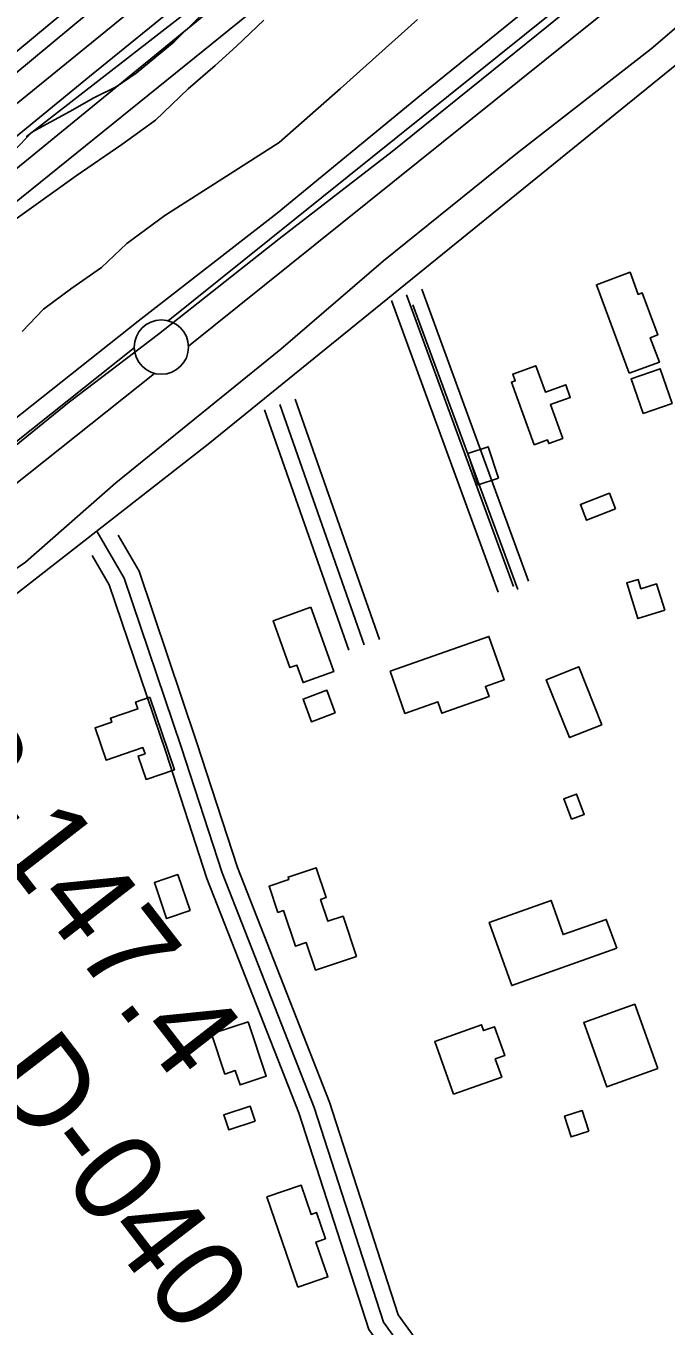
# Model space of a CAD drawing. Extents: x 3477039 to 3515015, y 546746 to 572297.
# Drawn here: x 3484351 to 3484941, y 556246 to 557444 of the extents above; entities that cross this region are included whole.
import ezdxf

# ---------------------------------------------------------------- set-up
doc = ezdxf.new("R2010")
doc.units = 0
for name, color, linetype in [('V-BLDG-OTLN', 7, 'Continuous'), ('V-FLOD-BASE', 7, 'Continuous'), ('V-LEVE-TOET', 7, 'Continuous'), ('V-RIVR-EDGE', 7, 'Continuous'), ('V-RIVR-RANG-IDEN', 7, 'Continuous'), ('V-ROAD-CNTR', 7, 'Continuous'), ('V-RRAP-RVMT', 7, 'Continuous'), ('V-RRAP-RVMT-IDEN', 7, 'Continuous'), ('V-SITE-VEGE', 7, 'Continuous'), ('V-SURV-LINE', 7, 'Continuous'), ('V-TOPO-DPTH', 7, 'Continuous'), ('V-TOPO-MINR', 7, 'Continuous'), ('V-TOPO-WATR', 7, 'Continuous')]:
    doc.layers.add(name, color=color, linetype=linetype)

msp = doc.modelspace()

# ---------------------------------------------------------------- linework, layer by layer
at = {"layer": 'V-BLDG-OTLN'}
for points in [[(3484906.9, 557124.2), (3484876.6, 557205.8), (3484907.6, 557217.3), (3484915.1, 557196.8), (3484918.8, 557198.2), (3484933.1, 557159.6), (3484926.3, 557157), (3484934.7, 557134.5)], [(3484819.3, 557058.4), (3484798.3, 557115.9), (3484801.8, 557117.2), (3484799.5, 557123.5), (3484820.7, 557131.2), (3484829.6, 557106.8), (3484848.4, 557113.6), (3484852.6, 557102), (3484834.2, 557095.3), (3484845.6, 557064.2), (3484832.7, 557059.5), (3484831.5, 557062.8)], [(3484919.8, 557087.2), (3484908.7, 557119.2), (3484935.3, 557128.4), (3484946.4, 557096.5)], [(3484786.4, 557027.5), (3484767.7, 557021.3), (3484758.1, 557050.3), (3484776.9, 557056.5)], [(3484894.2, 556999.2), (3484867.5, 556988.8), (3484861.9, 557003.4), (3484888.6, 557013.7)], [(3484939.7, 556905.9), (3484914.9, 556898.2), (3484904.6, 556931.1), (3484915.1, 556934.3), (3484917.7, 556925.7), (3484932.1, 556930.2)], [(3484613.4, 556908.6), (3484634.6, 556849.4), (3484606.3, 556839.3), (3484600.6, 556855.3), (3484594.3, 556853.1), (3484578.9, 556896.2)], [(3484686.5, 556849.6), (3484777.6, 556881.7), (3484791.6, 556841.7), (3484774.4, 556835.7), (3484777.7, 556826.3), (3484734.2, 556811), (3484730.5, 556821.5), (3484700.2, 556810.8)], [(3484881.6, 556800.4), (3484851.8, 556788.5), (3484830.4, 556841.9), (3484860.3, 556853.8)], [(3484636, 556811.3), (3484614, 556803.2), (3484606.4, 556824), (3484628.3, 556832.1)], [(3484465.1, 556825.7), (3484487.8, 556758.9), (3484461.7, 556750), (3484454.3, 556771.5), (3484460.8, 556773.7), (3484458.8, 556779.4), (3484424.8, 556767.8), (3484414.7, 556797.6), (3484430, 556802.8), (3484428.8, 556806.3), (3484454.2, 556815), (3484452, 556821.3)], [(3484853.6, 556713.4), (3484846.6, 556732.1), (3484858.4, 556736.5), (3484865.4, 556717.8)], [(3484502.2, 556629.2), (3484480.6, 556621.8), (3484469.3, 556655), (3484490.9, 556662.4)], [(3484655.6, 556587), (3484617.8, 556574.4), (3484609.3, 556599.7), (3484599.3, 556596.3), (3484588.3, 556629.1), (3484583.1, 556627.4), (3484575, 556651.6), (3484593.2, 556657.7), (3484592.5, 556660), (3484618.3, 556668.7), (3484627.6, 556641.1), (3484622.5, 556639.3), (3484629.2, 556619.3), (3484643.2, 556624)], [(3484895.3, 556594.4), (3484798.7, 556560), (3484777.9, 556618.2), (3484834.8, 556638.5), (3484846, 556607), (3484885.7, 556621.1)], [(3484933.3, 556483.6), (3484886.3, 556466.7), (3484865, 556526.1), (3484912, 556542.9)], [(3484555.7, 556526.7), (3484572.4, 556476.6), (3484548.3, 556468.5), (3484543.9, 556481.7), (3484534.4, 556478.5), (3484522.1, 556515.5)], [(3484745.1, 556460), (3484727.7, 556508.6), (3484770.8, 556523.9), (3484772.7, 556518.6), (3484782.7, 556522.2), (3484792.2, 556495.6), (3484783.4, 556492.5), (3484789.4, 556475.8)], [(3484562.2, 556435.1), (3484537.9, 556427.1), (3484533.3, 556440.9), (3484557.7, 556448.9)], [(3484869.7, 556425.8), (3484853.3, 556420.6), (3484847.3, 556439.8), (3484863.6, 556444.9)], [(3484601.4, 556282.1), (3484573, 556365.3), (3484604.6, 556376.1), (3484613.7, 556349.3), (3484618.6, 556351), (3484626.9, 556326.8), (3484618.2, 556323.8), (3484629.2, 556291.6)]]:
    msp.add_lwpolyline(points, close=True, dxfattribs=at)
at = {"layer": 'V-FLOD-BASE'}
for points in [[(3484584.2, 557248.1), (3484688.5, 557328.6), (3484832.6, 557444.5), (3484998.5, 557579.6), (3485118.7, 557679.8), (3485220.8, 557762.3)], [(3484584.2, 557248.1), (3484473, 557160.1), (3484391.2, 557098), (3484296, 557020.8), (3484214.8, 556958.1), (3484134.4, 556892.5), (3484070.7, 556842), (3484011.2, 556794.2), (3483940.6, 556737.5), (3483875.5, 556687), (3483799.9, 556624.2), (3483711.8, 556555.2), (3483611.7, 556476.8), (3483550.1, 556427.6), (3483472.5, 556367.5), (3483388.5, 556299.9), (3483319.3, 556245.3), (3483258.4, 556198.9), (3483194, 556144.3), (3483180.7, 556133.4)]]:
    msp.add_lwpolyline(points, dxfattribs=at)
at = {"layer": 'V-LEVE-TOET'}
for points in [[(3485177.7, 557755.5), (3485047.2, 557648.6), (3484890.4, 557523), (3484715.6, 557381.2), (3484582.4, 557271.7)], [(3484585.8, 557146.3), (3484680.4, 557227.8), (3484803.9, 557327.4), (3484927, 557423), (3485014.5, 557498.3), (3485065.3, 557537.9), (3485095.1, 557555.9), (3485107.2, 557560.7), (3485132.6, 557574.7), (3485167.1, 557598.2), (3485216, 557644.1), (3485266.1, 557696.4), (3485335.9, 557752.6)], [(3483140.8, 556159.5), (3483158.3, 556171.7), (3483165.9, 556174.8), (3483178.5, 556179.8), (3483192.4, 556181), (3483207, 556185.7), (3483253.1, 556217), (3483386.1, 556325.6), (3483505, 556421.9), (3483623.3, 556515.4), (3483740.1, 556608.3), (3483905.9, 556740), (3484042.4, 556847.9), (3484238.9, 557001.4), (3484454.4, 557172.1), (3484582.4, 557271.7)], [(3484585.8, 557146.3), (3484433.9, 557023.3), (3484350.6, 556950.2), (3484272.3, 556896.4), (3484164, 556818), (3484079.9, 556744.9), (3484015.6, 556695), (3483932.3, 556629.5), (3483839.3, 556558.6), (3483743.5, 556482.1), (3483676.9, 556425.4), (3483601.3, 556360.5), (3483551, 556324.3), (3483476.9, 556269.1), (3483403.4, 556209), (3483350.2, 556166.7), (3483302.6, 556125), (3483259.1, 556084.6), (3483213, 556049.8), (3483163.2, 556005.4)]]:
    msp.add_lwpolyline(points, dxfattribs=at)
at = {"layer": 'V-RIVR-EDGE'}
msp.add_lwpolyline([(3483504.1, 556660.2), (3483576.2, 556716.7), (3483682.7, 556810.1), (3483737.5, 556864.6), (3483810.3, 556925.1), (3483854.2, 556961.6), (3483939, 557022.6), (3484006.4, 557088.5), (3484040.1, 557123.2), (3484070.2, 557141.7), (3484108.1, 557171.1), (3484149, 557205.2), (3484189.9, 557236.9), (3484233.1, 557256.6), (3484300.5, 557304.5), (3484339.6, 557328.4), (3484356.4, 557346.4), (3484391.3, 557365.5), (3484413.5, 557378), (3484434, 557388.2), (3484452.6, 557400.7), (3484487.5, 557429.5), (3484527.2, 557469)], dxfattribs=at)
at = {"layer": 'V-ROAD-CNTR'}
for points in [[(3484980, 557432.6), (3484518.9, 557058.8), (3484236.1, 556838.3), (3484046.6, 556689.6), (3483814.6, 556500.6), (3483673.5, 556390.5), (3483557.4, 556297.9)], [(3484980, 557432.6), (3484518.9, 557058.8), (3484236.1, 556838.3), (3484046.6, 556689.6), (3483814.6, 556500.6), (3483673.5, 556390.5), (3483557.4, 556297.9)], [(3484715.8, 557201.7), (3484814.2, 556932.8)], [(3484687.7, 557191.4), (3484786, 556922.5)], [(3484701.7, 557196.6), (3484800.1, 556927.6)], [(3484707.6, 557187.4), (3484804.3, 556925.1)], [(3484585, 557095.3), (3484662.5, 556874)], [(3484599.1, 557100.3), (3484676.7, 556878.9)], [(3484570.8, 557090.4), (3484648.4, 556869)], [(3484416.3, 556978.8), (3484441.4, 556935.5), (3484494.1, 556780), (3484531.9, 556663.8), (3484616.6, 556447.7), (3484680.4, 556250), (3484793.8, 556093.4)], [(3484435.9, 556975.1), (3484455.2, 556941.8), (3484508.3, 556784.7), (3484546, 556668.9), (3484630.8, 556452.8), (3484693.9, 556256.8), (3484812, 556093.8)], [(3484412, 556956.4), (3484427.7, 556929.3), (3484479.9, 556775.3), (3484517.8, 556658.8), (3484602.5, 556442.7), (3484666.8, 556243.1), (3484782, 556084.1)]]:
    msp.add_lwpolyline(points, dxfattribs=at)
at = {"layer": 'V-RRAP-RVMT'}
msp.add_line((3484565.6, 557508.7), (3484351.1, 557342.1), dxfattribs=at)
at = {"layer": 'V-SITE-VEGE'}
for points in [[(3484333.5, 557260.4), (3484397.3, 557306.2), (3484439.4, 557334.9), (3484470.3, 557357.5), (3484500.6, 557386.4), (3484525.2, 557407.7), (3484544.9, 557425.5), (3484570.2, 557449.6)], [(3484711.8, 557450.1), (3484640.9, 557386.5), (3484584.2, 557336.7), (3484535.8, 557305.9), (3484479, 557269.7), (3484443.9, 557243.7), (3484420.7, 557221.7), (3484393.3, 557202.6), (3484367.3, 557183.4), (3484347.6, 557162.8)]]:
    msp.add_lwpolyline(points, dxfattribs=at)
at = {"layer": 'V-SURV-LINE'}
for points in [[(3484482, 557172.5), (3485468.6, 557964.5)], [(3484482, 557172.5), (3485468.6, 557964.5)], [(3485487.4, 557941.1), (3484500.7, 557149.1)], [(3485487.4, 557941.1), (3484500.7, 557149.1)], [(3483197.5, 556150.5), (3484450.8, 557147.6)], [(3483197.5, 556150.5), (3484450.8, 557147.6)], [(3484469.5, 557124.1), (3483216.2, 556127)], [(3484469.5, 557124.1), (3483216.2, 556127)]]:
    msp.add_lwpolyline(points, dxfattribs=at)
msp.add_circle((3484475.8, 557148.3), 25, dxfattribs=at)
at = {"layer": 'V-TOPO-DPTH'}
for points in [[(3484942.7, 557828.7), (3484926.3, 557815.5), (3484688.1, 557623.6), (3484595.1, 557548.5), (3484502.2, 557473.2), (3484409.6, 557397.7), (3484317, 557322.1), (3484180, 557209.7), (3484156.1, 557190.1), (3484132.2, 557170.5), (3484108.4, 557150.9), (3484084.5, 557131.3), (3483890.2, 556971.2), (3483795.1, 556892.4), (3483700.2, 556813.4), (3483605.8, 556733.8), (3483511.6, 556654), (3483352.1, 556517.9), (3483337.9, 556505.8), (3483323.9, 556493.6), (3483310, 556481.2), (3483296.1, 556468.8), (3483202.1, 556383.8), (3483141.3, 556328.9)], [(3484457.6, 557497.1), (3484124.3, 557220.5)], [(3484124.3, 557220.5), (3484457.6, 557497.1)]]:
    msp.add_lwpolyline(points, dxfattribs=at)
at = {"layer": 'V-TOPO-MINR'}
for points in [[(3483090.1, 556309.6), (3483264.9, 556471.2), (3483287.3, 556491.7), (3483309.8, 556512), (3483332.5, 556532.2), (3483355.3, 556552.2), (3483418.9, 556607.3), (3483473.8, 556654.6), (3483528.9, 556701.6), (3483584.4, 556748.2), (3483640.1, 556794.5), (3484052.7, 557134.8), (3484085.4, 557161.7), (3484118.1, 557188.7), (3484150.8, 557215.7), (3484183.6, 557242.6), (3484190, 557247.9), (3484226, 557277.4), (3484262, 557306.9), (3484298, 557336.4), (3484334.1, 557365.8), (3484890.9, 557819.1), (3484917.1, 557840.2), (3484943.3, 557861.3)], [(3483141.3, 556328.9), (3483202.1, 556383.8), (3483296.1, 556468.8), (3483310, 556481.2), (3483323.9, 556493.6), (3483337.9, 556505.8), (3483352.1, 556517.9), (3483511.6, 556654), (3483605.8, 556733.8), (3483700.2, 556813.4), (3483795.1, 556892.4), (3483890.2, 556971.2), (3484084.5, 557131.3), (3484108.4, 557150.9), (3484132.2, 557170.5), (3484156.1, 557190.1), (3484180, 557209.7), (3484317, 557322.1), (3484409.6, 557397.7), (3484502.2, 557473.2), (3484595.1, 557548.5), (3484688.1, 557623.6), (3484926.3, 557815.5), (3484942.7, 557828.7)], [(3483190.7, 556468.6), (3483205.4, 556482.5), (3483220.2, 556496.3), (3483235.2, 556509.8), (3483250.4, 556523.2), (3483274.9, 556544.7), (3483277.9, 556547.2), (3483280.9, 556549.8), (3483283.9, 556552.3), (3483286.9, 556554.8), (3483877.7, 557037.8), (3483914.2, 557067.6), (3483950.6, 557097.4), (3483987.1, 557127.2), (3484023.5, 557157.1), (3484034.7, 557166.2), (3484065.5, 557191.5), (3484096.3, 557216.8), (3484127.1, 557242.2), (3484157.8, 557267.7), (3484757.8, 557765.6)], [(3483185.6, 556343.4), (3483215.6, 556370.3), (3483245.7, 556397.2), (3483275.8, 556424), (3483323.7, 556466.4), (3483329.9, 556471.9), (3483336.3, 556477.4), (3483342.6, 556482.8), (3483349, 556488.2), (3483733.4, 556810.9), (3483801.8, 556868.2), (3483870.4, 556925.4), (3483939.2, 556982.3), (3484008.1, 557039.2), (3484115.8, 557127.8), (3484130.9, 557140.2), (3484146.1, 557152.6), (3484161.2, 557165.1), (3484176.4, 557177.5), (3484634.5, 557551.9)], [(3484172.8, 557145.7), (3484680.1, 557555.5)]]:
    msp.add_lwpolyline(points, dxfattribs=at)
at = {"layer": 'V-TOPO-WATR'}
msp.add_lwpolyline([(3484124.3, 557220.5), (3484457.6, 557497.1)], dxfattribs=at)

# ---------------------------------------------------------------- texts
at = {"layer": 'V-RIVR-RANG-IDEN'}
for s, rotation, p in [('R-147.4', 307.7657, (3484247.5, 556781)), ('D-040', 307.5394, (3484312.6, 556474.9))]:
    msp.add_text(s, height=83, rotation=rotation, dxfattribs=at).set_placement(p)
at = {"layer": 'V-RRAP-RVMT-IDEN'}
msp.add_text('REVET.', height=100, rotation=37.7778, dxfattribs=at).set_placement((3484181.2, 557425))

doc.saveas('drawing.dxf')
